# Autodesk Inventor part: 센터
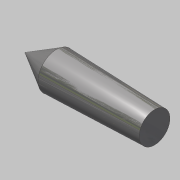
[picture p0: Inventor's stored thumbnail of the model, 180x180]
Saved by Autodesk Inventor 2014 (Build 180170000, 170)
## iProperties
Created: 2019-10
Part Number: 센터
Material: 스테인리스강
Document SubType Name: Modeling
Designer: mduedu
Density: 1 g/cm^3
Appearance: 반광택
Author: mduedu
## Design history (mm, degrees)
sketch "스케치1"
  geometry: L1 (0, 0)-(-31.5, 0); L2 (-31.5, 0)-(-31.5, -0.125); L3 (-31.5, -0.125)-(-23.922, -4.5); L4 (-23.922, -4.5)-(0, -3.751); L5 (0, -3.751)-(0, 0)
  constraints: 10 end point, 1 horizontal, 1 parallel, 1 perpendicular
  dimensions: "d0" = 31.5 distance of L1.start L1.end; "d1" = 7.502 diameter of L4.end L1; "d2" = 30 deg angle of L1 L3; "d3" = 7.578 horizontal distance of L2.end L3.end; "d5" = 0.25 diameter of L2.end L1; "d6" = 23.922 horizontal distance of L3.end L4.end (derived); "d7" = 9.00032 diameter of L3.end L1 (derived)
revolve "회전1" sketch "스케치1" stored, may be unused: angle "d8" = 90 deg
node "솔리드1"
